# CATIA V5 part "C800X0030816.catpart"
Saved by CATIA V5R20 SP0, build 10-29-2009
Part number: C800X0030816
Source: Unknown
Property "A": "30"
Property "ARTICLENO": "C800X0030816"
Property "B": "13"
Property "BOMINFO": "C800X0030816"
Property "C": "46"
Property "CA": "C800X0030816"
Property "D1": "38"
Property "DES": "ROTATING EYEBOLT WITH RING Ton 0,3 M8x16"
Property "E": "50"
Property "H": "105"
Property "L": "16"
Property "LINA": "C800X0030816"
Property "NB": "C800X0030816"
Property "NBSYN": "$CODE."
Property "NN": "C800X"
Property "NT": "Rotating eyebolt with ring"
Property "SIZE": "M8"
Property "SUPPLIER": "CF"
Property "SW": "30"
Property "WEIGHT": "480"
Property "WLL": "0.30"
Bounding box of the stored display mesh (mm): x -27.983 to 27.983, y -16 to 117.837, z -19 to 19
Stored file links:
  C:\Users\Utente\Desktop\3D files 800X\C800X0030816.catpart

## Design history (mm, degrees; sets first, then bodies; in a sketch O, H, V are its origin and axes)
Body1 "Geometry.1" (main body)
  Solid1 "C800X0030816.catpart": solid without history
